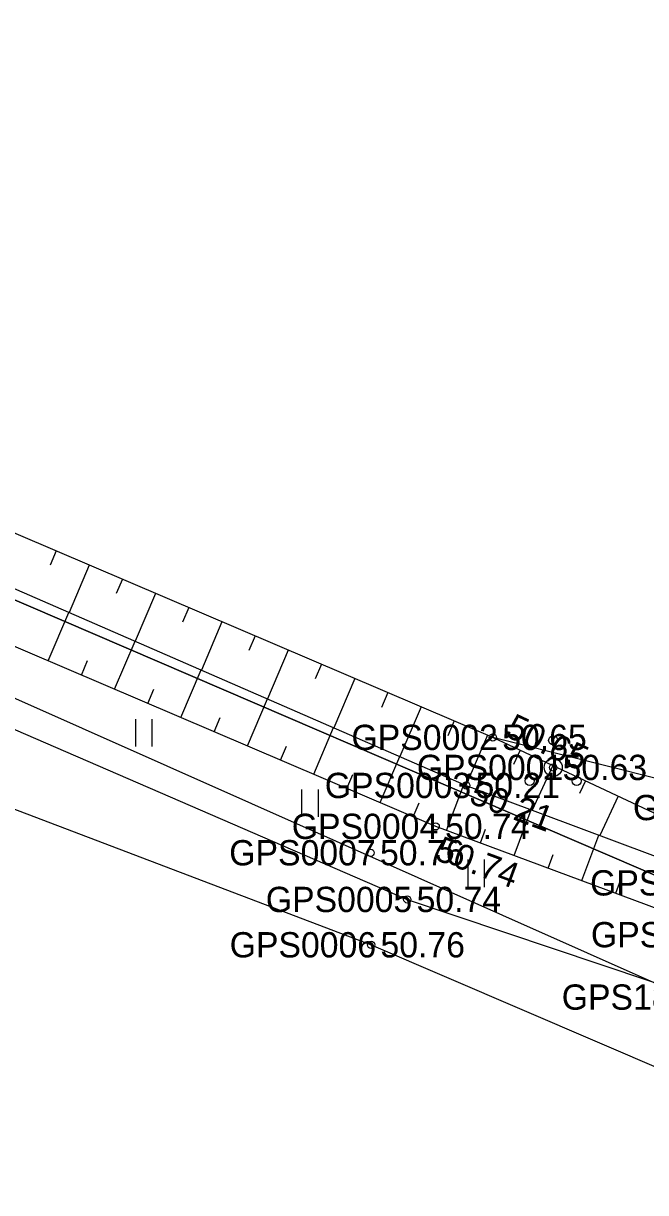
# Model space of a CAD drawing. Extents: x 551623 to 559850, y 6561220 to 6567135.
# Drawn here: x 556170.6 to 556187.85, y 6565291.91 to 6565324.29 of the extents above; entities that cross this region are included whole.
import ezdxf

# ---------------------------------------------------------------- set-up
doc = ezdxf.new("R2010")
doc.units = 0
for name, color, linetype in [('HALJASTUS', 7, 'Continuous'), ('KORGUS-EH2000', 7, 'Continuous'), ('KPOHULIIN', 7, 'Continuous'), ('MOOTKORG-EH2000', 7, 'Continuous'), ('MOOTMPUNKT', 7, 'Continuous'), ('MOOTNR', 7, 'Continuous'), ('MOOTPIIR', 7, 'Continuous'), ('PIIR', 7, 'Continuous'), ('PUU', 7, 'Continuous'), ('RELJEEF', 7, 'Continuous')]:
    doc.layers.add(name, color=color, linetype=linetype)

msp = doc.modelspace()

# ---------------------------------------------------------------- linework, layer by layer
at = {"layer": 'HALJASTUS'}
for p, q in [((556173.71, 6565305.023), (556173.71, 6565304.262)), ((556174.165, 6565305.023), (556174.165, 6565304.262)), ((556178.317, 6565303.078), (556178.317, 6565302.317)), ((556178.772, 6565303.078), (556178.772, 6565302.317)), ((556182.923, 6565301.134), (556182.923, 6565300.372)), ((556183.378, 6565301.134), (556183.378, 6565300.372))]:
    msp.add_line(p, q, dxfattribs=at)
msp.add_lwpolyline([(556046.78, 6565342.989), (556063.163, 6565343.594), (556068.98, 6565343.227), (556088.001, 6565339.172), (556129.048, 6565322.123), (556145.114, 6565315.754), (556160.903, 6565308.821), (556181.243, 6565300.029), (556189.306, 6565297.325), (556192.704, 6565293.427)], dxfattribs=at)
at = {"layer": 'KORGUS-EH2000'}
for centre in [(556183.617, 6565304.516), (556182.877, 6565303.186), (556182.032, 6565302.053), (556181.243, 6565300.029), (556180.241, 6565298.772)]:
    msp.add_circle(centre, 0.1, dxfattribs=at)
at = {"layer": 'KPOHULIIN'}
msp.add_lwpolyline([(555766.29, 6565358.132), (555774.476, 6565357.809), (555774.476, 6565357.809), (555822.758, 6565358.143), (555870.36, 6565358.416), (555918.911, 6565358.624), (555918.911, 6565358.624), (555966.511, 6565359.063), (556012.012, 6565359.614), (556063.102, 6565345.172), (556063.102, 6565345.172), (556112.628, 6565331.115), (556160.567, 6565309.951), (556211.02, 6565287.529)], dxfattribs=at)
at = {"layer": 'MOOTMPUNKT'}
for centre in [(556183.617, 6565304.516), (556185.289, 6565303.685), (556182.877, 6565303.186), (556182.032, 6565302.053), (556180.228, 6565301.322), (556181.243, 6565300.029), (556180.241, 6565298.772)]:
    msp.add_circle(centre, 0.1, dxfattribs=at)
at = {"layer": 'MOOTPIIR'}
for points in [[(556317.29, 6565325.671), (556298.007, 6565323.148), (556292.386, 6565325.238), (556233.701, 6565312.976), (556223.169, 6565308.85), (556214.051, 6565308.489), (556203.216, 6565309.397), (556197.609, 6565310.789), (556194.429, 6565307.325), (556191.934, 6565304.799), (556191.351, 6565302.574), (556183.617, 6565304.516), (556162.392, 6565313.566), (556146.837, 6565320.486), (556131.546, 6565328.064), (556116.861, 6565334.423), (556089.682, 6565344.853), (556063.899, 6565353.523), (556057.929, 6565353.821), (556039.198, 6565356.19)], [(556038.736, 6565344.782), (556063.163, 6565343.594), (556086.721, 6565336.994), (556111.614, 6565326.991), (556127.814, 6565320.014), (556144.527, 6565313.178), (556160.096, 6565306.424), (556180.241, 6565298.772), (556192.704, 6565293.427), (556201.956, 6565286.07), (556200.431, 6565280.098), (556196.227, 6565270.783), (556185.467, 6565248.994)]]:
    msp.add_lwpolyline(points, dxfattribs=at)
at = {"layer": 'PIIR'}
for points in [[(556340.11, 6565662.55), (556389.4, 6565609.96), (556364.34, 6565374.53), (556350.73, 6565342.07), (556335.44, 6565331.24), (556229.81, 6565311.25), (556213.87, 6565303.19), (556199.38, 6565295.85), (556122.95, 6565328.71), (556145.23, 6565518.55)], [(555766.77, 6565362.31), (555785.15, 6565359.9), (555792.17, 6565359.86), (555889.86, 6565359.34), (555986.85, 6565360.88), (556065.95, 6565349.3), (556122.95, 6565328.71), (556199.38, 6565295.85), (556198.85, 6565282.81), (556195.83, 6565275.41), (556189.32, 6565262.35), (556176.88, 6565235.57), (556133.25, 6565139.15), (556097.67, 6565060.64), (555982.17, 6564796.57), (555965.54, 6564731.83), (555935.2, 6564801.96), (555871.92, 6565015.39), (555870.22, 6565021.13), (555867.36, 6565030.76)]]:
    msp.add_lwpolyline(points, close=True, dxfattribs=at)
at = {"layer": 'PUU'}
for centre, radius in [((556185.289, 6565304.435), 0.125), ((556185.289, 6565303.685), 0.25), ((556184.639, 6565303.31), 0.125), ((556185.939, 6565303.31), 0.125)]:
    msp.add_circle(centre, radius, dxfattribs=at)
at = {"layer": 'RELJEEF'}
for p, q in [((556171.508, 6565309.68), (556171.341, 6565309.289)), ((556172.428, 6565309.287), (556171.869, 6565307.977)), ((556173.348, 6565308.895), (556173.179, 6565308.5)), ((556174.267, 6565308.503), (556173.703, 6565307.179)), ((556171.292, 6565306.636), (556171.865, 6565307.979)), ((556175.187, 6565308.111), (556175.017, 6565307.712)), ((556176.107, 6565307.719), (556175.537, 6565306.381)), ((556173.132, 6565305.851), (556173.699, 6565307.181)), ((556177.027, 6565307.326), (556176.855, 6565306.923)), ((556177.947, 6565306.934), (556177.371, 6565305.583)), ((556172.212, 6565306.244), (556172.383, 6565306.645)), ((556174.971, 6565305.066), (556175.533, 6565306.383)), ((556178.867, 6565306.542), (556178.693, 6565306.134)), ((556179.787, 6565306.15), (556179.205, 6565304.785)), ((556174.052, 6565305.459), (556174.221, 6565305.856)), ((556180.707, 6565305.757), (556180.531, 6565305.346)), ((556176.811, 6565304.281), (556177.367, 6565305.585)), ((556175.891, 6565304.674), (556176.059, 6565305.067)), ((556181.626, 6565305.365), (556181.039, 6565303.987)), ((556178.65, 6565303.496), (556179.201, 6565304.786)), ((556182.546, 6565304.973), (556182.369, 6565304.557)), ((556183.466, 6565304.581), (556182.872, 6565303.188)), ((556177.73, 6565303.889), (556177.896, 6565304.278)), ((556184.374, 6565304.162), (556184.19, 6565303.77)), ((556180.49, 6565302.711), (556181.035, 6565303.988)), ((556179.57, 6565303.104), (556179.734, 6565303.489)), ((556185.28, 6565303.738), (556184.702, 6565302.504)), ((556182.335, 6565301.94), (556182.808, 6565303.216)), ((556186.185, 6565303.313), (556186.022, 6565302.965)), ((556187.091, 6565302.889), (556186.581, 6565301.801)), ((556181.409, 6565302.318), (556181.572, 6565302.7)), ((556184.21, 6565301.245), (556184.68, 6565302.512)), ((556183.272, 6565301.592), (556183.414, 6565301.973)), ((556186.085, 6565300.549), (556186.554, 6565301.812)), ((556185.147, 6565300.897), (556185.288, 6565301.276)), ((556187.023, 6565300.201), (556187.163, 6565300.579))]:
    msp.add_line(p, q, dxfattribs=at)
for points in [[(556028.747, 6565357.937), (556030.86, 6565357.563), (556039.198, 6565356.19), (556057.929, 6565353.821), (556064.592, 6565351.829), (556088.936, 6565343.79), (556116.503, 6565332.956), (556130.776, 6565326.047), (556146.22, 6565319.093), (556161.9, 6565312.316), (556182.877, 6565303.186), (556190.092, 6565300.488), (556198.955, 6565296.142)], [(556198.951, 6565295.377), (556198.427, 6565295.218), (556190.116, 6565299.053), (556182.032, 6565302.053), (556161.506, 6565310.813), (556145.447, 6565317.76), (556130.182, 6565324.921), (556115.272, 6565331.25), (556088.426, 6565342.556), (556064.014, 6565350.434), (556058.394, 6565352.289), (556039.035, 6565355.08), (556031.391, 6565355.68), (556030.571, 6565354.761), (556029.124, 6565354.87), (556026.62, 6565346.439)], [(556199.481, 6565296.508), (556199.264, 6565296.85), (556195.086, 6565299.143), (556183.617, 6565304.516), (556162.392, 6565313.566), (556146.837, 6565320.486), (556131.546, 6565328.064), (556116.861, 6565334.423), (556089.682, 6565344.853), (556063.899, 6565353.523), (556057.923, 6565355.027)]]:
    msp.add_lwpolyline(points, dxfattribs=at)

# ---------------------------------------------------------------- texts
at = {"layer": 'KORGUS-EH2000'}
for s, rotation, p in [(' 50.65', 334.8966, (556183.691, 6565304.675)), (' 50.21', 339.497, (556182.682, 6565302.802)), (' 50.74', 339.6431, (556181.728, 6565301.232))]:
    msp.add_text(s, height=0.7, rotation=rotation, dxfattribs=at).set_placement(p)
for s, p in [(' 50.74', (556181.243, 6565299.679)), (' 50.76', (556180.241, 6565298.423))]:
    msp.add_text(s, height=0.7, dxfattribs=at).set_placement(p)
at = {"layer": 'MOOTKORG-EH2000'}
for s, p in [(' 50.65', (556183.617, 6565304.167)), (' 50.63', (556185.289, 6565303.335)), (' 50.21', (556182.877, 6565302.836)), (' 50.74', (556182.032, 6565301.703)), (' 50.76', (556180.228, 6565300.972)), (' 50.74', (556181.243, 6565299.679)), (' 50.76', (556180.241, 6565298.423))]:
    msp.add_text(s, height=0.7, dxfattribs=at).set_placement(p)
at = {"layer": 'MOOTNR'}
for s, p in [('GPS0002 ', (556179.697, 6565304.167)), ('GPS0001 ', (556181.509, 6565303.335)), ('GPS0003 ', (556178.958, 6565302.836)), ('GPS1849 ', (556187.501, 6565302.224)), ('GPS0004 ', (556178.043, 6565301.703)), ('GPS0007 ', (556176.309, 6565300.972)), ('GPS1850 ', (556186.312, 6565300.138)), ('GPS0005 ', (556177.323, 6565299.679)), ('GPS1856 ', (556186.336, 6565298.703)), ('GPS0006 ', (556176.321, 6565298.423)), ('GPS1855 ', (556185.526, 6565296.975))]:
    msp.add_text(s, height=0.7, dxfattribs=at).set_placement(p)

doc.saveas('drawing.dxf')
